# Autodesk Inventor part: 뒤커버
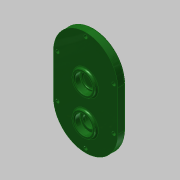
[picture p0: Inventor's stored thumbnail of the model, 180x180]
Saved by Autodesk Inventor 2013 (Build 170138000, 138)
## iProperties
Created: 2016-12
Part Number: 뒤커버
Material: 알루미늄 6061
Document SubType Name: Modeling
Designer: mduedu
Density: 2.71 g/cm^3
Author: mduedu
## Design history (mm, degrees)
sketch "스케치1"
  geometry: L1 (40, -25)-(40, 25); L2 (-40, 25)-(-40, -25); L3 (-40, -25)-(40, 25); L4 (40, -25)-(-40, 25); A1 r 40 centre (0, 25) between (40, 25) and (-40, 25); A2 r 40 centre (0, -25) between (-40, -25) and (40, -25); 1 further point
  constraints: 8 end point, 4 point on circle, 4 tangent, 2 centre point, 2 midpoint, 1 parallel, 1 vertical
  dimensions: "d0" = 130 dimension on A2 A1; "d2" = 80 distance between parallel lines of L1 L2
extrude "돌출1" new body sketch "스케치1" distance "d3" = 10; taper "d4" = 0 deg
sketch "스케치2"
  geometry: C1 r 14 at (0, 11); 1 further point
  constraints: 1 centre point, 1 vertical alignment
  dimensions: "d5" = 28 diameter of C1; "d6" = 11 distance of C1.centre point (0, 0)
extrude "돌출2" join sketch "스케치2" distance "d7" = 3; taper "d8" = 0 deg
sketch "스케치3"
  geometry: C1 r 14 at (0, -33.1); C2 r 14 at (0, 11) reference; 1 further point
  constraints: 1 centre point, 1 vertical alignment
  dimensions: "d9" = 28 diameter of C1; "d69" = 44.1 distance of C1.centre C2.centre
extrude "돌출3" join sketch "스케치3" distance "d11" = 3; taper "d12" = 0 deg
hole "구멍1" diameter "d15" = 22; stored, may be unused: countersink angle "d19" = 90 deg, drill point angle "d21" = 0 deg; dims "d13" = 10, "d14" = 10, "d16" = 6, "d17" = 4, "d18" = 2, "d20" = 7
hole "구멍2" diameter "d24" = 18; stored, may be unused: countersink angle "d28" = 90 deg, drill point angle "d30" = 0 deg; dims "d22" = 10, "d23" = 10, "d25" = 6, "d26" = 4, "d27" = 2, "d29" = 1
hole "구멍3" diameter "d33" = 22; stored, may be unused: countersink angle "d37" = 90 deg, drill point angle "d39" = 0 deg; dims "d31" = 10, "d32" = 10, "d34" = 6, "d35" = 4, "d36" = 2, "d38" = 7
sketch "스케치4"
  geometry: C1 r 14 at (0, -33.1) reference; C2 r 18 at (0, -33.1); 1 further point
  constraints: 1 centre point, 1 coincident
  dimensions: "d40" = 36 diameter of C2
extrude "돌출4" join sketch "스케치4" distance "d41" = 4; taper "d42" = 0 deg
hole "구멍4" diameter "d45" = 22; stored, may be unused: countersink angle "d49" = 90 deg, drill point angle "d51" = 0 deg; dims "d46" = 6, "d47" = 4, "d48" = 2, "d50" = 7.3, "d80" = 10, "d81" = 10
hole "구멍5" diameter "d54" = 15; stored, may be unused: countersink angle "d58" = 90 deg, drill point angle "d60" = 0 deg; dims "d52" = 10, "d53" = 10, "d55" = 6, "d56" = 4, "d57" = 2, "d59" = 7
fillet "모깎기1" dims "d61" = 0.3
fillet "모깎기2" dims "d62" = 2
chamfer "모따기1" distance "d63" = 1; stored, may be unused: second distance "d64" = 2, angle "d65" = 45 deg
chamfer "모따기2" distance "d82" = 0.7; stored, may be unused: second distance "d83" = 2, angle "d84" = 30 deg
fillet "모깎기3" dims "d66" = 2
fillet "모깎기4" dims "d67" = 2
fillet "모깎기5" dims "d68" = 2
sketch "스케치5"
  geometry: L1 (-40, 25)-(-40, -25) reference; L2 (40, -25)-(40, 25) reference; L3 (35, 25)-(35, -25); L4 (-35, -25)-(-35, 25); A1 r 40 centre (0, 25) between (40, 25) and (-40, 25) reference; A2 r 40 centre (0, -25) between (-40, -25) and (40, -25) reference; A3 r 35 centre (0, 25) between (35, 25) and (-35, 25); A4 r 35 centre (0, -25) between (-35, -25) and (35, -25); 2 further points
  constraints: 5 point on circle, 4 end point, 2 centre point, 1 vertical alignment, 3 other
  dimensions: "d70" = 5 distance between parallel lines of L2 L3
sketch "스케치6"
  geometry: 1 further point
  constraints: 1 other
hole "구멍6" sketch "스케치6" at (0, 60) diameter "d71" = 4.5; stored, may be unused: countersink angle "d75" = 90 deg, drill point angle "d77" = 0 deg; dims "d72" = 6, "d73" = 8, "d74" = 4.6, "d76" = 8
node "솔리드1"
pattern_linear "직사각형 패턴1"
